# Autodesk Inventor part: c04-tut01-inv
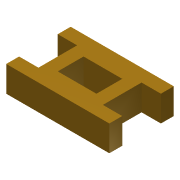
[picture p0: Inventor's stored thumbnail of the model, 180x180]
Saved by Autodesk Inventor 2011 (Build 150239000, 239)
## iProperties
Created: 2010-01
Part Number: c04-tut01-inv
Document SubType Name: Modeling
Designer: CADSoft
Density: 1 g/cm^3
Author: CADSoft
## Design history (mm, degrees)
sketch "Sketch1"
  geometry: L1 (80, 0)-(0, 0); L2 (0, 0)-(0, 10); L3 (0, 10)-(15, 10); L4 (15, 10)-(15, 40); L5 (15, 40)-(0, 40); L6 (0, 40)-(0, 50); L7 (0, 50)-(80, 50); L8 (80, 50)-(80, 40); L9 (80, 40)-(65, 40); L10 (65, 40)-(65, 10); L11 (65, 10)-(80, 10); L12 (80, 10)-(80, 0); L13 (25, 35)-(55, 35); L14 (55, 35)-(55, 15); L15 (55, 15)-(25, 15); L16 (25, 15)-(25, 35); 2 further points
  constraints: 32 end point, 9 equal length, 7 horizontal, 6 vertical, 2 coincident, 1 other
  dimensions: "d1" = 80 distance of L1.start L1.end; "d2" = 10 distance of L1.end L2.end; "d3" = 30 distance of L3.end L4.end; "d4" = 20 distance of L13.end L14.end; "d5" = 30 distance of L13.start L13.end; "d6" = 10 distance between parallel lines of L16 L4; "d7" = 10 distance between parallel lines of L10 L14; "d8" = 15 distance between parallel lines of L15 L1
extrude "Extrusion1" new body sketch "Sketch1" distance "d9" = 20; taper "d10" = 0 deg
body "Solid1"
